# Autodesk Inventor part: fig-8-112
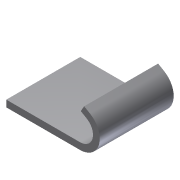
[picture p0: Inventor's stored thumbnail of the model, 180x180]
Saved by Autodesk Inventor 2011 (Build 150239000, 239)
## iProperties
Created: 2009-09
Part Number: fig-8-112
Document SubType Name: Modeling
Designer: Sham
Density: 1 g/cm^3
Author: Sham
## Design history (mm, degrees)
sketch "Sketch1"
  geometry: L1 (-33.976, 22)-(0, 22); L2 (0, 22)-(0, 0); L3 (0, 0)-(-33.976, 0); L4 (-33.976, 0)-(-33.976, 22)
  constraints: 8 end point, 2 parallel, 1 horizontal, 1 perpendicular
extrude "Extrusion1" new body sketch "Sketch1" distance "d0" = 2; taper "d1" = 0 deg
sketch "Sketch2"
  geometry: L1 (-12, 22)-(-12, 0)
  constraints: 2 end point
feature "Bend Part1" sketch "Sketch2" dims "d4" = 10, "d5" = 150 deg
body "Solid1"
